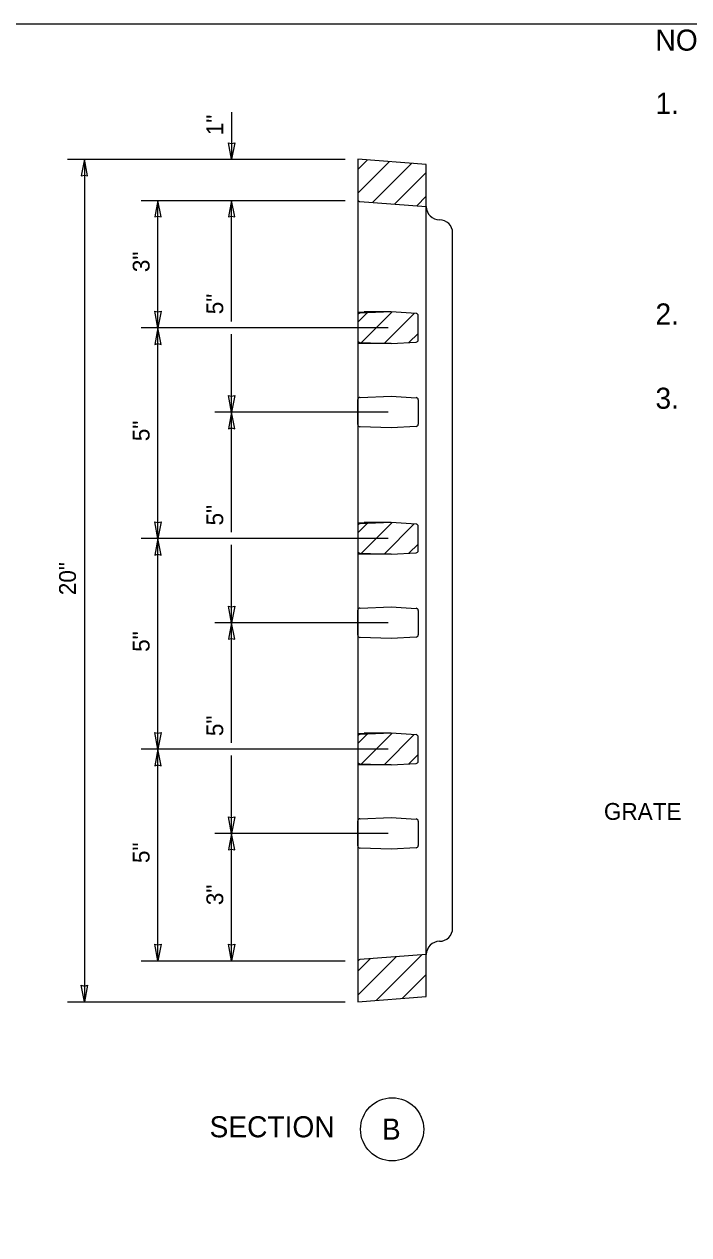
# Model space of a CAD drawing. Extents: x 99862 to 103151, y 100000 to 102076.
# Drawn here: x 101491 to 102122, y 100926 to 102076 of the extents above; entities that cross this region are included whole.
import ezdxf

# ---------------------------------------------------------------- set-up
doc = ezdxf.new("R2010")
doc.units = 0
for name, color, linetype in [('Level 1', 7, 'Continuous'), ('Level 15', 7, 'Continuous'), ('Level 17', 7, 'Continuous'), ('Level 2', 7, 'Continuous'), ('Level 20', 7, 'Continuous'), ('Level 9', 7, 'Continuous')]:
    doc.layers.add(name, color=color, linetype=linetype)

msp = doc.modelspace()

# ---------------------------------------------------------------- linework, layer by layer
at = {"layer": 'Level 1'}
for p, q in [((101808, 101909.2), (101808, 101185.3)), ((101898, 101217.3), (101898, 101877.3))]:
    msp.add_line(p, q, dxfattribs=at)
msp.add_lwpolyline([(99862, 99999.5), (103151, 99999.5), (103151, 102075.5), (99862, 102075.5)], close=True, dxfattribs=at)
for centre, start, end in [((101885.5, 101902.3), 180, 270), ((101885.5, 101877.3), 0, 90), ((101885.5, 101217.3), 270, 0), ((101885.5, 101192.3), 90, 180)]:
    msp.add_arc(centre, 12.5, start, end, dxfattribs=at)
at = {"layer": 'Level 15'}
for p, q in [((101688, 101992.1), (101688, 101947.3)), ((101532, 101947.3), (101796, 101947.3)), ((101548, 101947.3), (101548, 101147.3)), ((101602, 101908.2), (101796, 101908.2)), ((101618, 101787.3), (101618, 101908.2)), ((101688, 101793.3), (101688, 101908.2)), ((101836.6, 101787.3), (101602, 101787.3)), ((101618, 101587.3), (101618, 101787.3)), ((101688, 101707.3), (101688, 101781.3)), ((101836.6, 101707.3), (101672, 101707.3)), ((101688, 101593.3), (101688, 101707.3)), ((101836.6, 101587.3), (101602, 101587.3)), ((101618, 101387.3), (101618, 101587.3)), ((101688, 101507.3), (101688, 101581.3)), ((101836.6, 101507.3), (101672, 101507.3)), ((101688, 101393.3), (101688, 101507.3)), ((101836.6, 101387.3), (101602, 101387.3)), ((101618, 101186.3), (101618, 101387.3)), ((101688, 101307.3), (101688, 101381.3)), ((101836.6, 101307.3), (101672, 101307.3)), ((101688, 101186.3), (101688, 101307.3)), ((101602, 101186.3), (101796, 101186.3)), ((101532, 101147.3), (101796, 101147.3))]:
    msp.add_line(p, q, dxfattribs=at)
for points in [[(101688, 101947.3), (101684.9, 101963), (101688, 101962.3), (101691, 101963)], [(101548, 101947.3), (101544.9, 101931.5), (101548, 101932.3), (101551, 101931.5)], [(101618, 101908.2), (101614.9, 101892.5), (101618, 101893.2), (101621, 101892.5)], [(101688, 101908.2), (101684.9, 101892.5), (101688, 101893.2), (101691, 101892.5)], [(101618, 101787.3), (101614.9, 101803), (101618, 101802.3), (101621, 101803)], [(101618, 101787.3), (101614.9, 101771.5), (101618, 101772.3), (101621, 101771.5)], [(101688, 101707.3), (101684.9, 101723), (101688, 101722.3), (101691, 101723)], [(101688, 101707.3), (101684.9, 101691.5), (101688, 101692.3), (101691, 101691.5)], [(101618, 101587.3), (101614.9, 101603), (101618, 101602.3), (101621, 101603)], [(101618, 101587.3), (101614.9, 101571.5), (101618, 101572.3), (101621, 101571.5)], [(101688, 101507.3), (101684.9, 101523), (101688, 101522.3), (101691, 101523)], [(101688, 101507.3), (101684.9, 101491.5), (101688, 101492.3), (101691, 101491.5)], [(101618, 101387.3), (101614.9, 101403), (101618, 101402.3), (101621, 101403)], [(101618, 101387.3), (101614.9, 101371.5), (101618, 101372.3), (101621, 101371.5)], [(101688, 101307.3), (101684.9, 101323), (101688, 101322.3), (101691, 101323)], [(101688, 101307.3), (101684.9, 101291.5), (101688, 101292.3), (101691, 101291.5)], [(101618, 101186.3), (101614.9, 101202), (101618, 101201.3), (101621, 101202)], [(101688, 101186.3), (101684.9, 101202), (101688, 101201.3), (101691, 101202)], [(101548, 101147.3), (101544.9, 101163), (101548, 101162.3), (101551, 101163)]]:
    msp.add_lwpolyline(points, close=True, dxfattribs=at)
at = {"layer": 'Level 17'}
for p, q in [((101817, 101946.6), (101808, 101937.6)), ((101838, 101945), (101808, 101915)), ((101859, 101943.3), (101821.8, 101906.2)), ((101873, 101934.7), (101842.9, 101904.6)), ((101873, 101912.1), (101863.9, 101903)), ((101816.8, 101801.4), (101808, 101792.6)), ((101840.2, 101802.2), (101811.3, 101773.3)), ((101861.6, 101801), (101833.1, 101772.5)), ((101865.3, 101782), (101856.5, 101773.2)), ((101816.8, 101601.4), (101808, 101592.6)), ((101840.2, 101602.2), (101811.3, 101573.3)), ((101861.6, 101601), (101833.1, 101572.5)), ((101865.3, 101582), (101856.5, 101573.2)), ((101816.8, 101401.4), (101808, 101392.6)), ((101840.2, 101402.2), (101811.3, 101373.3)), ((101861.6, 101401), (101833.1, 101372.5)), ((101865.3, 101382), (101856.5, 101373.2)), ((101844.3, 101190.1), (101808, 101153.7)), ((101819.8, 101188.2), (101808, 101176.3)), ((101868.8, 101192), (101825.5, 101148.6)), ((101873, 101173.4), (101850, 101150.5))]:
    msp.add_line(p, q, dxfattribs=at)
at = {"layer": 'Level 2'}
for p, q in [((101873, 101192.3), (101873, 101902.3)), ((101839.7, 101802.3), (101814.1, 101802.3)), ((101839.7, 101772.3), (101814.1, 101772.3)), ((101839.7, 101602.3), (101814.1, 101602.3)), ((101839.7, 101572.3), (101814.1, 101572.3)), ((101839.7, 101402.3), (101814.1, 101402.3)), ((101839.7, 101372.3), (101814.1, 101372.3))]:
    msp.add_line(p, q, dxfattribs=at)
for points in [[(101809.9, 101907.1), (101873, 101902.3), (101873, 101942.3), (101808, 101947.3), (101808, 101909.2)], [(101808, 101799.1), (101808, 101775.4)], [(101863.3, 101800.9), (101839.7, 101802.3), (101810, 101801.2)], [(101865.3, 101775.7), (101865.3, 101798.9)], [(101810, 101773.3), (101839.7, 101772.3), (101863.3, 101773.6)], [(101808, 101695.4), (101808, 101719.1)], [(101810, 101721.2), (101839.7, 101722.3), (101863.3, 101720.9)], [(101865.3, 101718.9), (101865.3, 101695.7)], [(101863.3, 101693.6), (101839.7, 101692.3), (101810, 101693.3)], [(101863.3, 101600.9), (101839.7, 101602.3), (101810, 101601.2)], [(101808, 101599.1), (101808, 101575.4)], [(101865.3, 101575.7), (101865.3, 101598.9)], [(101810, 101573.3), (101839.7, 101572.3), (101863.3, 101573.6)], [(101810, 101521.2), (101839.7, 101522.3), (101863.3, 101520.9)], [(101808, 101495.4), (101808, 101519.1)], [(101865.3, 101518.9), (101865.3, 101495.7)], [(101863.3, 101493.6), (101839.7, 101492.3), (101810, 101493.3)], [(101808, 101399.1), (101808, 101375.4)], [(101863.3, 101400.9), (101839.7, 101402.3), (101810, 101401.2)], [(101865.3, 101375.7), (101865.3, 101398.9)], [(101810, 101373.3), (101839.7, 101372.3), (101863.3, 101373.6)], [(101808, 101295.4), (101808, 101319.1)], [(101810, 101321.2), (101839.7, 101322.3), (101863.3, 101320.9)], [(101865.3, 101318.9), (101865.3, 101295.7)], [(101863.3, 101293.6), (101839.7, 101292.3), (101810, 101293.3)], [(101808, 101185.3), (101808, 101147.3), (101873, 101152.3), (101873, 101192.3), (101809.9, 101187.4)]]:
    msp.add_lwpolyline(points, dxfattribs=at)
for centre, start, end in [((101810, 101909.2), 180, 265.6013), ((101810, 101799.1), 92.0522, 180), ((101863.2, 101798.9), 360, 86.758), ((101810, 101775.4), 180, 267.9478), ((101863.2, 101775.7), 273.242, 0), ((101810, 101719.1), 92.0522, 180), ((101863.2, 101718.9), 0, 86.758), ((101810, 101695.4), 180, 267.9478), ((101863.2, 101695.7), 273.242, 0), ((101810, 101599.1), 92.0522, 180), ((101863.2, 101598.9), 360, 86.758), ((101810, 101575.4), 180, 267.9478), ((101863.2, 101575.7), 273.242, 0), ((101810, 101519.1), 92.0522, 180), ((101863.2, 101518.9), 0, 86.758), ((101810, 101495.4), 180, 267.9478), ((101863.2, 101495.7), 273.242, 0), ((101810, 101399.1), 92.0522, 180), ((101863.2, 101398.9), 360, 86.758), ((101810, 101375.4), 180, 267.9478), ((101863.2, 101375.7), 273.242, 0), ((101810, 101319.1), 92.0522, 180), ((101863.2, 101318.9), 0, 86.758), ((101810, 101295.4), 180, 267.9478), ((101863.2, 101295.7), 273.242, 0), ((101810, 101185.3), 94.3987, 180)]:
    msp.add_arc(centre, 2.09, start, end, dxfattribs=at)
for centre, major_axis, start_param, end_param in [((101813, 101802.4), (5, 0.18), 3.139963, 4.946409), ((101813, 101772.1), (-5, 0.18), 4.478369, 6.284815), ((101813, 101602.4), (5, 0.18), 3.139963, 4.946409), ((101813, 101572.1), (-5, 0.18), 4.478369, 6.284815), ((101813, 101402.4), (5, 0.18), 3.139963, 4.946409), ((101813, 101372.1), (-5, 0.18), 4.478369, 6.284815)]:
    msp.add_ellipse(centre, major_axis=major_axis, ratio=0.045396, start_param=start_param, end_param=end_param, dxfattribs=at)
at = {"layer": 'Level 9'}
msp.add_circle((101840.5, 101026.3), 30, dxfattribs=at)

# ---------------------------------------------------------------- texts
at = {"layer": 'Level 20'}
for s, height, p in [('NOTES', 20, (102090.8, 102050.4)), ('1.', 20, (102090.8, 101990.4)), ('2.', 20, (102090.8, 101790.4)), ('3.', 20, (102090.8, 101710.4)), ('GRATE', 16, (102041.8, 101320.1)), ('SECTION', 20, (101667, 101018.7)), ('B', 20, (101830.8, 101016.5))]:
    msp.add_text(s, height=height, dxfattribs=at).set_placement(p)
for s, p in [('1"', (101680, 101970.1)), ('3"', (101610, 101840.1)), ('5"', (101680, 101800.1)), ('5"', (101610, 101679.6)), ('5"', (101680, 101599.6)), ('20"', (101540, 101533.4)), ('5"', (101610, 101479.6)), ('5"', (101680, 101399.6)), ('5"', (101610, 101279.1)), ('3"', (101680, 101239.1))]:
    msp.add_text(s, height=16, rotation=90, dxfattribs=at).set_placement(p)

doc.saveas('drawing.dxf')
